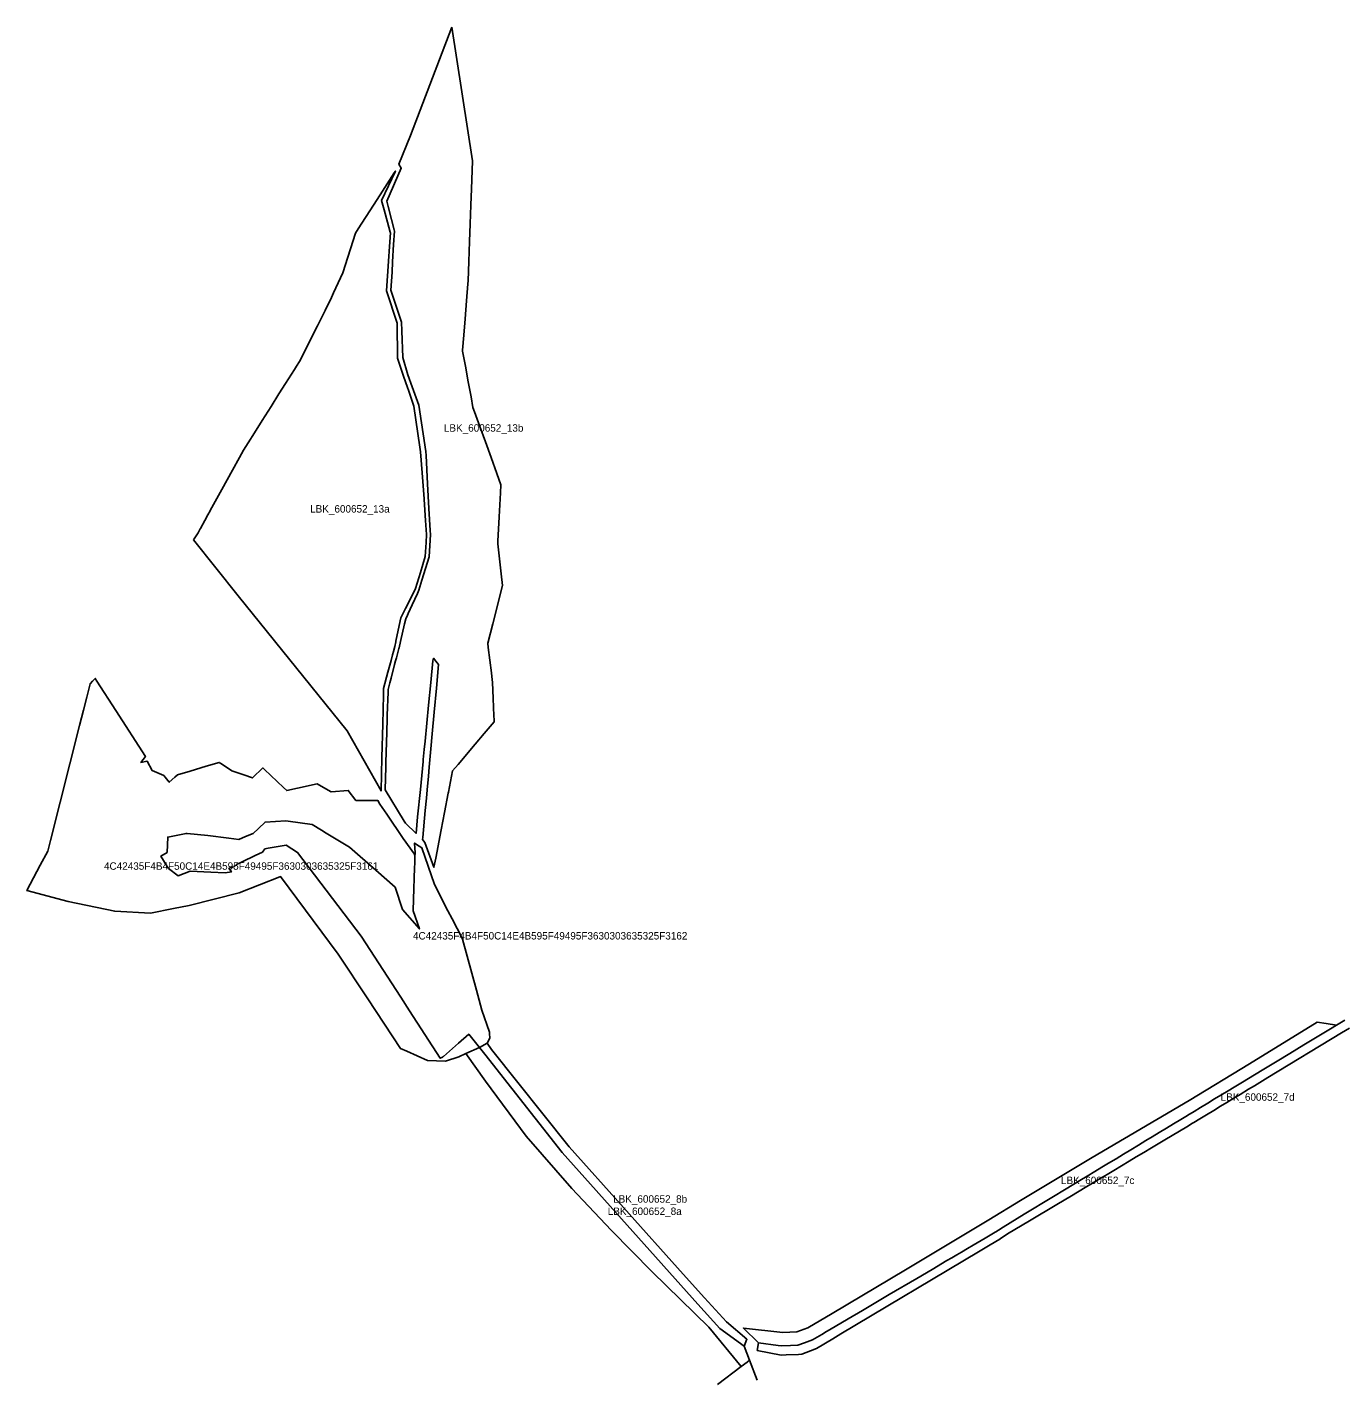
# Model space of a CAD drawing. Extents: x -537012 to -534434, y -1176840 to -1172739.
# Drawn here: x -537012 to -536126, y -1174115 to -1173206 of the extents above; entities that cross this region are included whole.
import ezdxf

# ---------------------------------------------------------------- set-up
doc = ezdxf.new("R2010")
doc.units = 0
for name, color, linetype in [('91270013', 7, 'Continuous'), ('91270023', 7, 'Continuous'), ('91280013', 7, 'Continuous'), ('91280023', 7, 'Continuous')]:
    doc.layers.add(name, color=color, linetype=linetype)

msp = doc.modelspace()

# ---------------------------------------------------------------- linework, layer by layer
at = {"layer": '91270013'}
msp.add_lwpolyline([(-536702.47, -1173890.09), (-536707.68, -1173892.89), (-536714.87, -1173884.03), (-536721.7, -1173890.01), (-536731.89, -1173898.94), (-536732, -1173899), (-536732.55, -1173899.32), (-536734.01, -1173900.15), (-536754.68, -1173868.25), (-536760.66, -1173859.02), (-536787.3, -1173817.89), (-536830.09, -1173761.6), (-536837.77, -1173756.69), (-536849.97, -1173758.79), (-536852.1, -1173759.16), (-536853.81, -1173761.35), (-536858.57, -1173763.62), (-536867.38, -1173767.81), (-536871.29, -1173769.67), (-536872.8, -1173771.25), (-536876.37, -1173772.2), (-536874.65, -1173774.65), (-536878.89, -1173775.4), (-536888.41, -1173774.93), (-536902.39, -1173774.23), (-536910.62, -1173777.35), (-536917.12, -1173772.33), (-536917.89, -1173771.05), (-536922.12, -1173764.02), (-536917.94, -1173761.52), (-536917.53, -1173751.18), (-536905.17, -1173748.77), (-536904.38, -1173748.85), (-536890.58, -1173750.19), (-536876.38, -1173751.98), (-536869.68, -1173752.83), (-536865.19, -1173750.93), (-536860.1, -1173748.79), (-536856.5, -1173745.4), (-536852, -1173741.16), (-536837.94, -1173740.26), (-536836.39, -1173740.47), (-536820.25, -1173742.68), (-536813.97, -1173746.6), (-536810.75, -1173748.61), (-536795.16, -1173757.93), (-536777.49, -1173773.43), (-536764.31, -1173784.99), (-536759.46, -1173799.92), (-536748.01, -1173813.08), (-536752.33, -1173800.78), (-536752.06, -1173792.98), (-536751.34, -1173771.89), (-536751.23, -1173768.8), (-536751.08, -1173764.33), (-536750.99, -1173761.73), (-536751.28, -1173755.27), (-536748.12, -1173757.31), (-536746.46, -1173758.38), (-536737.9, -1173783.19), (-536728.87, -1173800.79), (-536726.06, -1173806.27), (-536719.34, -1173819.36), (-536719.02, -1173819.99), (-536709.66, -1173854.32), (-536706.01, -1173867.7), (-536700.88, -1173882.54), (-536700.84, -1173883.54), (-536700.72, -1173886.71)], close=True, dxfattribs=at)
at = {"layer": '91270023'}
msp.add_lwpolyline([(-536716.72, -1173897.04), (-536721.42, -1173899.2), (-536730.59, -1173902.07), (-536742.7, -1173901.73), (-536756.6, -1173895.44), (-536760.91, -1173893.49), (-536782.87, -1173860.22), (-536802.78, -1173830.06), (-536841.57, -1173777.83), (-536842.06, -1173777.98), (-536869.5, -1173788.82), (-536903.14, -1173797.26), (-536913.6, -1173799.22), (-536929.05, -1173802.37), (-536953.24, -1173801.18), (-536984.68, -1173794.53), (-537012.32, -1173787.26), (-537003.41, -1173770.23), (-536998.3, -1173760.8), (-536996.52, -1173753.5), (-536976.89, -1173676.04), (-536974.28, -1173665.76), (-536972.08, -1173657.08), (-536969.8, -1173648.07), (-536968.14, -1173646.29), (-536966.39, -1173644.41), (-536965.23, -1173646.2), (-536952.52, -1173665.92), (-536932.53, -1173696.93), (-536935.6, -1173700.95), (-536931.45, -1173700.04), (-536928.11, -1173706.3), (-536920.26, -1173709.8), (-536916.56, -1173714.28), (-536912.74, -1173710.88), (-536910.9, -1173709.24), (-536902.41, -1173706.75), (-536891.59, -1173703.57), (-536882.88, -1173701.01), (-536880.69, -1173702.42), (-536874.31, -1173706.54), (-536868.89, -1173708.43), (-536866.29, -1173709.34), (-536860.56, -1173711.34), (-536853.61, -1173704.66), (-536852.43, -1173705.78), (-536839.52, -1173717.94), (-536837.38, -1173719.95), (-536830.12, -1173718.3), (-536816.89, -1173715.3), (-536814.12, -1173716.89), (-536807.52, -1173720.67), (-536795.97, -1173719.79), (-536790.84, -1173726.67), (-536790.16, -1173726.67), (-536775.96, -1173726.62), (-536774.64, -1173729.06), (-536770.1, -1173735.75), (-536758.9, -1173752.25), (-536751.36, -1173762.78), (-536751.08, -1173764.33), (-536751.23, -1173768.8), (-536751.34, -1173771.89), (-536752.06, -1173792.98), (-536752.33, -1173800.78), (-536748.01, -1173813.08), (-536759.46, -1173799.92), (-536764.31, -1173784.99), (-536777.49, -1173773.43), (-536795.16, -1173757.93), (-536810.75, -1173748.61), (-536813.97, -1173746.6), (-536820.25, -1173742.68), (-536836.39, -1173740.47), (-536837.94, -1173740.26), (-536852, -1173741.16), (-536856.5, -1173745.4), (-536860.1, -1173748.79), (-536865.19, -1173750.93), (-536869.68, -1173752.83), (-536876.38, -1173751.98), (-536890.58, -1173750.19), (-536904.38, -1173748.85), (-536905.17, -1173748.77), (-536917.53, -1173751.18), (-536917.94, -1173761.52), (-536922.12, -1173764.02), (-536917.89, -1173771.05), (-536917.12, -1173772.33), (-536910.62, -1173777.35), (-536902.39, -1173774.23), (-536888.41, -1173774.93), (-536878.89, -1173775.4), (-536874.65, -1173774.65), (-536876.37, -1173772.2), (-536872.8, -1173771.25), (-536871.29, -1173769.67), (-536867.38, -1173767.81), (-536858.57, -1173763.62), (-536853.81, -1173761.35), (-536852.1, -1173759.16), (-536849.97, -1173758.79), (-536837.77, -1173756.69), (-536830.09, -1173761.6), (-536787.3, -1173817.89), (-536760.66, -1173859.02), (-536754.68, -1173868.25), (-536734.01, -1173900.15), (-536732.55, -1173899.32), (-536732, -1173899), (-536731.89, -1173898.94), (-536721.7, -1173890.01), (-536714.87, -1173884.03), (-536707.68, -1173892.89)], close=True, dxfattribs=at)
at = {"layer": '91280013'}
for points in [[(-536726.26, -1173205.78), (-536712.23, -1173295.85), (-536712.48, -1173302.36), (-536712.95, -1173314.83), (-536713.37, -1173325.78), (-536713.85, -1173338.23), (-536714.31, -1173350.16), (-536714.83, -1173363.76), (-536715.32, -1173376.77), (-536715.4, -1173378.79), (-536716.34, -1173390.11), (-536717.35, -1173402.33), (-536718.26, -1173413.33), (-536719.1, -1173423.47), (-536719, -1173424.01), (-536717.13, -1173434.13), (-536715.17, -1173444.76), (-536713.3, -1173454.89), (-536712, -1173461.94), (-536710.97, -1173464.79), (-536707.33, -1173474.88), (-536703.66, -1173485.04), (-536699.85, -1173495.61), (-536695.94, -1173506.43), (-536693.21, -1173513.98), (-536693.52, -1173519.44), (-536694.43, -1173535.65), (-536695.35, -1173551.97), (-536695.15, -1173553.77), (-536692.92, -1173573.88), (-536692.05, -1173581.74), (-536698.67, -1173607.59), (-536702.04, -1173620.74), (-536701.68, -1173623.61), (-536699.58, -1173640.61), (-536699, -1173645.28), (-536698.8, -1173646.92), (-536698.34, -1173657.82), (-536697.84, -1173669.52), (-536697.81, -1173672.19), (-536697.8, -1173673.62), (-536704.46, -1173681.52), (-536710.47, -1173688.63), (-536722.04, -1173702.34), (-536725.71, -1173706.69), (-536728.51, -1173721.08), (-536728.63, -1173721.7), (-536731.14, -1173734.61), (-536733.42, -1173746.36), (-536737.11, -1173765.41), (-536738.3, -1173771.53), (-536744.48, -1173754.89), (-536745.92, -1173752.89), (-536745.77, -1173751.42), (-536744.12, -1173733.44), (-536743.36, -1173725.12), (-536742.84, -1173719.42), (-536741.99, -1173710.19), (-536741.43, -1173704.08), (-536740.3, -1173691.71), (-536739.38, -1173681.66), (-536738.04, -1173667.04), (-536736.58, -1173651.07), (-536735.1, -1173634.97), (-536736.99, -1173632.72), (-536738.62, -1173630.78), (-536738.92, -1173632.56), (-536740.35, -1173647.13), (-536741.85, -1173662.4), (-536744.22, -1173686.61), (-536744.78, -1173692.27), (-536745.43, -1173698.9), (-536745.57, -1173700.32), (-536747.43, -1173719.3), (-536749.24, -1173737.69), (-536750.32, -1173748.72), (-536757.48, -1173741.93), (-536758.32, -1173740.53), (-536771.08, -1173719.32), (-536770.65, -1173704.01), (-536770.6, -1173702.35), (-536770.57, -1173701.06), (-536769.99, -1173680.61), (-536769.46, -1173661.95), (-536769.43, -1173660.62), (-536769.18, -1173651.83), (-536768.01, -1173647.37), (-536767.15, -1173644.12), (-536764.76, -1173635.05), (-536764.13, -1173632.64), (-536763.55, -1173630.46), (-536761.89, -1173624.15), (-536761.8, -1173623.8), (-536760.81, -1173619.57), (-536758.04, -1173607.71), (-536757.23, -1173604.24), (-536756.13, -1173601.84), (-536755.59, -1173600.65), (-536752.9, -1173594.78), (-536749.42, -1173587.19), (-536748.45, -1173585.08), (-536746.36, -1173578.24), (-536741.57, -1173562.61), (-536740.66, -1173547.43), (-536740.8, -1173544.87), (-536741.62, -1173530.03), (-536742.54, -1173513.34), (-536743.58, -1173494.26), (-536743.73, -1173491.55), (-536748.44, -1173460.44), (-536752.87, -1173448.15), (-536755.82, -1173439.97), (-536759.21, -1173428.41), (-536759.86, -1173410.37), (-536760.07, -1173404.43), (-536767.21, -1173383.01), (-536766.5, -1173370.87), (-536766.1, -1173363.95), (-536765.41, -1173352.16), (-536764.89, -1173343.17), (-536765.07, -1173342.46), (-536766.85, -1173335.32), (-536769.02, -1173326.62), (-536769.92, -1173323), (-536760.29, -1173300.9), (-536761.91, -1173298.23), (-536754.11, -1173278.82)], [(-536900.13, -1173551.19), (-536897.15, -1173546.32), (-536895.96, -1173544.15), (-536895.72, -1173543.73), (-536895.52, -1173543.35), (-536892.58, -1173538.02), (-536890.52, -1173534.27), (-536889.05, -1173531.62), (-536888.66, -1173530.9), (-536887.8, -1173529.34), (-536881.06, -1173517.1), (-536873.99, -1173504.27), (-536869.22, -1173495.62), (-536866.57, -1173490.8), (-536863.34, -1173485.69), (-536859.16, -1173479.05), (-536853.98, -1173470.84), (-536847.94, -1173461.26), (-536842.65, -1173452.86), (-536838.18, -1173445.78), (-536832.27, -1173436.41), (-536830.84, -1173434.15), (-536828.87, -1173431.02), (-536826.22, -1173425.75), (-536821.63, -1173416.6), (-536816.78, -1173406.94), (-536811.63, -1173396.67), (-536807.24, -1173387.92), (-536805.86, -1173384.88), (-536799.66, -1173371.28), (-536791.11, -1173344.5), (-536789.23, -1173341.58), (-536778.96, -1173325.66), (-536774.53, -1173318.78), (-536765.04, -1173304.06), (-536764.23, -1173302.81), (-536773.59, -1173322.71), (-536771.89, -1173328.86), (-536769.61, -1173337.09), (-536767.72, -1173343.88), (-536767.58, -1173344.39), (-536768.19, -1173353.64), (-536768.85, -1173363.54), (-536770.17, -1173383.46), (-536762.97, -1173405.24), (-536762.75, -1173428.76), (-536758.67, -1173440.8), (-536756.08, -1173448.57), (-536755.51, -1173450.29), (-536751.91, -1173461.06), (-536747.73, -1173488.68), (-536747.24, -1173491.91), (-536746.21, -1173506.04), (-536744.94, -1173523.42), (-536744.91, -1173523.88), (-536743.87, -1173538.18), (-536743.18, -1173547.58), (-536743.51, -1173552.94), (-536744.08, -1173562.31), (-536747.31, -1173573.02), (-536750.59, -1173583.92), (-536754.28, -1173591.21), (-536757.32, -1173597.22), (-536759.83, -1173602.17), (-536760.6, -1173603.69), (-536763, -1173615.11), (-536763.91, -1173619.41), (-536763.98, -1173619.76), (-536764.65, -1173622.95), (-536765.52, -1173626.2), (-536766.13, -1173628.47), (-536767.15, -1173632.27), (-536769.28, -1173640.22), (-536772.2, -1173651.13), (-536772.3, -1173655.41), (-536772.79, -1173675.2), (-536773.34, -1173697.65), (-536773.89, -1173720.12), (-536796.82, -1173679.68), (-536870.03, -1173588.72)], [(-536702.47, -1173890.09), (-536699.42, -1173894.17), (-536647.23, -1173959.79), (-536610.71, -1174000.56), (-536570.46, -1174045.5), (-536556.08, -1174061.56), (-536541.22, -1174077.55), (-536527.55, -1174089.36), (-536529.27, -1174094.11), (-536545.85, -1174082.18), (-536560.66, -1174065.67), (-536651.93, -1173963.52), (-536704.04, -1173897.38), (-536707.68, -1173892.89)]]:
    msp.add_lwpolyline(points, close=True, dxfattribs=at)
msp.add_lwpolyline([(-536121.73, -1173879.82), (-536127.22, -1173883.05), (-536176.7, -1173913.11), (-536185.79, -1173918.63), (-536189.8, -1173921.07), (-536195.38, -1173924.46), (-536199.57, -1173927.01), (-536204.4, -1173929.95), (-536208.57, -1173932.48), (-536213.16, -1173935.27), (-536218.04, -1173938.23), (-536222.45, -1173940.91), (-536226.54, -1173943.39), (-536227.42, -1173943.93), (-536231.29, -1173946.25), (-536236.3, -1173949.25), (-536241.08, -1173952.11), (-536246, -1173955.05), (-536250.59, -1173957.8), (-536255.11, -1173960.5), (-536260.16, -1173963.52), (-536265.33, -1173966.62), (-536270.12, -1173969.49), (-536275.36, -1173972.62), (-536280.48, -1173975.69), (-536284.89, -1173978.33), (-536289.57, -1173981.13), (-536294.82, -1173984.27), (-536299.82, -1173987.26), (-536309.03, -1173992.77), (-536318.71, -1173998.56), (-536337.32, -1174009.7), (-536351.98, -1174018.47), (-536352.31, -1174018.69), (-536354.72, -1174020.24), (-536357, -1174021.72), (-536357.31, -1174021.92), (-536363.65, -1174025.71), (-536371.59, -1174030.46), (-536464.2, -1174085.8), (-536469.57, -1174089.01), (-536480.57, -1174095.59), (-536484.71, -1174097.18), (-536490.52, -1174099.41), (-536492.89, -1174099.52), (-536500.99, -1174099.88), (-536504.45, -1174100.04), (-536520.56, -1174096.89), (-536519.81, -1174091.88), (-536506.47, -1174093.52), (-536504.12, -1174093.81), (-536498.18, -1174093.56), (-536493.33, -1174093.35), (-536488.7, -1174091.7), (-536486.93, -1174091.07), (-536483.39, -1174089.81), (-536477.07, -1174086.08), (-536473.9, -1174084.21), (-536473.56, -1174084.01), (-536468.2, -1174080.85), (-536459.25, -1174075.58), (-536449.69, -1174069.95), (-536431.62, -1174059.3), (-536413.11, -1174048.39), (-536402.81, -1174042.32), (-536392.81, -1174036.42), (-536389.47, -1174034.45), (-536386.11, -1174032.47), (-536382.96, -1174030.62), (-536378.98, -1174028.27), (-536375.12, -1174025.99), (-536367.07, -1174021.24), (-536360.44, -1174017.34), (-536360.3, -1174017.26), (-536359.97, -1174017.04), (-536358.13, -1174015.83), (-536356.37, -1174014.68), (-536355.33, -1174014.01), (-536355, -1174013.79), (-536340.85, -1174005.23), (-536322.18, -1173993.93), (-536312.57, -1173988.11), (-536303.28, -1173982.49), (-536298.34, -1173979.5), (-536293.15, -1173976.36), (-536288.49, -1173973.54), (-536284.02, -1173970.84), (-536278.95, -1173967.77), (-536273.84, -1173964.67), (-536269.08, -1173961.79), (-536263.89, -1173958.65), (-536258.88, -1173955.62), (-536254.51, -1173952.98), (-536249.9, -1173950.19), (-536245.06, -1173947.26), (-536240.18, -1173944.31), (-536235.25, -1173941.33), (-536230.77, -1173938.62), (-536230.5, -1173938.46), (-536226.43, -1173935.99), (-536221.98, -1173933.29), (-536217.1, -1173930.33), (-536212.56, -1173927.58), (-536208.34, -1173925.02), (-536203.54, -1173922.11), (-536199.34, -1173919.56), (-536193.84, -1173916.22), (-536189.66, -1173913.69), (-536180.47, -1173908.12), (-536170.43, -1173902.03), (-536162.02, -1173896.93), (-536152.44, -1173891.12), (-536143.43, -1173885.65), (-536134.51, -1173880.24), (-536130.48, -1173877.8), (-536124.97, -1173874.53)], dxfattribs=at)
at = {"layer": '91280023'}
for points in [[(-536519.81, -1174091.88), (-536529.84, -1174081.82), (-536503.22, -1174084.89), (-536494, -1174084.47), (-536486.42, -1174081.59), (-536470.01, -1174071.96), (-536420.7, -1174042.51), (-536364.52, -1174008.91), (-536343.36, -1173995.97), (-536295.01, -1173966.93), (-536229.61, -1173928.51), (-536189.18, -1173903.97), (-536143.4, -1173875.91), (-536137.45, -1173876.78), (-536130.48, -1173877.8), (-536134.51, -1173880.24), (-536143.43, -1173885.65), (-536152.44, -1173891.12), (-536162.02, -1173896.93), (-536170.43, -1173902.03), (-536180.47, -1173908.12), (-536189.66, -1173913.69), (-536193.84, -1173916.22), (-536199.34, -1173919.56), (-536203.54, -1173922.11), (-536208.34, -1173925.02), (-536212.56, -1173927.58), (-536217.1, -1173930.33), (-536221.98, -1173933.29), (-536226.43, -1173935.99), (-536230.5, -1173938.46), (-536230.77, -1173938.62), (-536235.25, -1173941.33), (-536240.18, -1173944.31), (-536245.06, -1173947.26), (-536249.9, -1173950.19), (-536254.51, -1173952.98), (-536258.88, -1173955.62), (-536263.89, -1173958.65), (-536269.08, -1173961.79), (-536273.84, -1173964.67), (-536278.95, -1173967.77), (-536284.02, -1173970.84), (-536288.49, -1173973.54), (-536293.15, -1173976.36), (-536298.34, -1173979.5), (-536303.28, -1173982.49), (-536312.57, -1173988.11), (-536322.18, -1173993.93), (-536340.85, -1174005.23), (-536355, -1174013.79), (-536355.33, -1174014.01), (-536356.37, -1174014.68), (-536358.13, -1174015.83), (-536359.97, -1174017.04), (-536360.3, -1174017.26), (-536360.44, -1174017.34), (-536367.07, -1174021.24), (-536375.12, -1174025.99), (-536378.98, -1174028.27), (-536382.96, -1174030.62), (-536386.11, -1174032.47), (-536389.47, -1174034.45), (-536392.81, -1174036.42), (-536402.81, -1174042.32), (-536413.11, -1174048.39), (-536431.62, -1174059.3), (-536449.69, -1174069.95), (-536459.25, -1174075.58), (-536468.2, -1174080.85), (-536473.56, -1174084.01), (-536473.9, -1174084.21), (-536477.07, -1174086.08), (-536483.39, -1174089.81), (-536486.93, -1174091.07), (-536488.7, -1174091.7), (-536493.33, -1174093.35), (-536498.18, -1174093.56), (-536504.12, -1174093.81), (-536506.47, -1174093.52)], [(-536525.77, -1174103.45), (-536527.4, -1174104.68), (-536531.3, -1174107.64), (-536553.25, -1174081.23), (-536591.39, -1174043.89), (-536618.92, -1174015.95), (-536645.34, -1173987.75), (-536676.1, -1173952.69), (-536703.54, -1173915.67), (-536716.72, -1173897.04), (-536707.68, -1173892.89), (-536704.04, -1173897.38), (-536651.93, -1173963.52), (-536560.66, -1174065.67), (-536545.85, -1174082.18), (-536529.27, -1174094.11)]]:
    msp.add_lwpolyline(points, close=True, dxfattribs=at)
msp.add_lwpolyline([(-536547.35, -1174119.82), (-536531.3, -1174107.64), (-536527.4, -1174104.68), (-536525.77, -1174103.45), (-536520.69, -1174116.97)], dxfattribs=at)

# ---------------------------------------------------------------- texts
at = {"layer": '91270013'}
msp.add_text('4C42435F4B4F50C14E4B595F49495F3630303635325F3162', height=5, rotation=360, dxfattribs=at).set_placement((-536752.38, -1173820.2))
at = {"layer": '91270023'}
msp.add_text('4C42435F4B4F50C14E4B595F49495F3630303635325F3161', height=5, rotation=360, dxfattribs=at).set_placement((-536960.46, -1173773.24))
at = {"layer": '91280013'}
for s, rotation, p in [('LBK_600652_13b', 0, (-536731.57, -1173478.25)), ('LBK_600652_13a', 360, (-536821.65, -1173532.74)), ('LBK_600652_7d', 0, (-536208.51, -1173928.78)), ('LBK_600652_8b', 360, (-536617.61, -1173997.39))]:
    msp.add_text(s, height=5, rotation=rotation, dxfattribs=at).set_placement(p)
at = {"layer": '91280023'}
for s, p in [('LBK_600652_7c', (-536316.03, -1173984.86)), ('LBK_600652_8a', (-536621.24, -1174005.67))]:
    msp.add_text(s, height=5, rotation=0, dxfattribs=at).set_placement(p)

doc.saveas('drawing.dxf')
